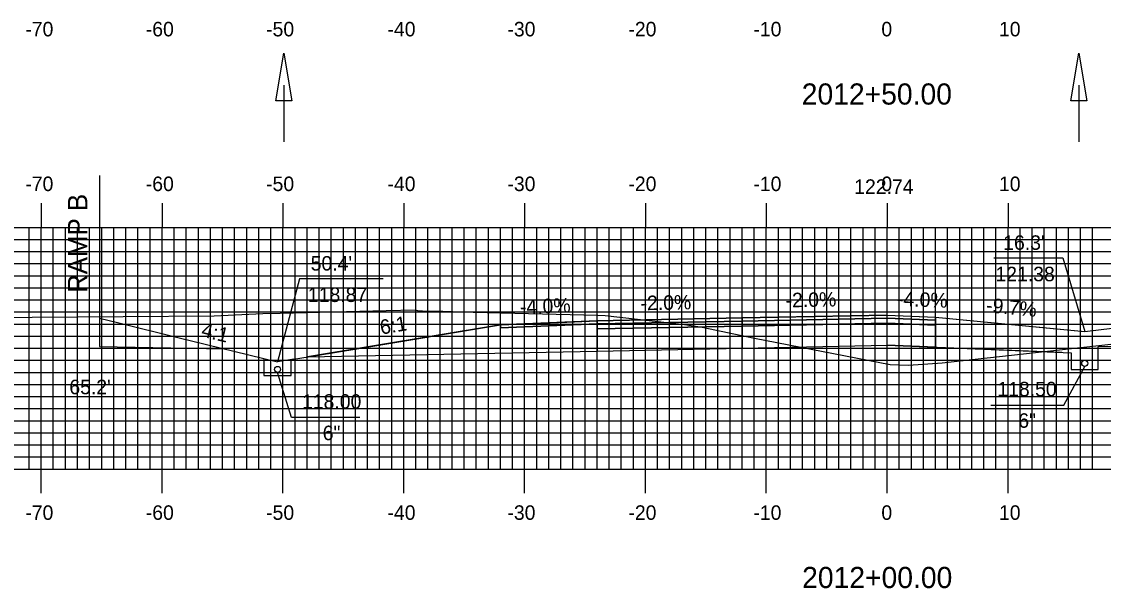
# Model space of a CAD drawing. Extents: x 853894 to 854237, y 366605 to 366825.
# Drawn here: x 853987.9 to 854077.4, y 366658.2 to 366705.1 of the extents above; entities that cross this region are included whole.
import ezdxf

# ---------------------------------------------------------------- set-up
doc = ezdxf.new("R2010")
doc.units = 0
for name, color, linetype in [('ANNOTATION', 7, 'Continuous'), ('D_Drainage_Ditch_Line', 7, 'Continuous'), ('D_Drainage_Underdrain', 7, 'Continuous'), ('D_Roadway_Centerline', 7, 'Continuous'), ('D_Roadway_Centerline_Text', 7, 'Continuous'), ('D_Roadway_Edge_Shoulder', 7, 'Continuous'), ('D_Roadway_Edge_TW', 7, 'Continuous'), ('D_Roadway_Pavement', 7, 'Continuous'), ('D_Roadway_SubGrade', 7, 'Continuous'), ('D_Text_Standard', 7, 'Continuous'), ('H_V ANNOTATION', 7, 'Continuous'), ('M_Roadway_Centerline', 7, 'Continuous'), ('MAJOR', 7, 'Continuous'), ('MINOR', 7, 'Continuous'), ('PDRAIN', 7, 'Continuous'), ('S_Roadway_Centerline', 7, 'Continuous')]:
    doc.layers.add(name, color=color, linetype=linetype)

msp = doc.modelspace()

# ---------------------------------------------------------------- linework, layer by layer
at = {"layer": 'ANNOTATION'}
for points in [[(854068.366, 366685.519), (854074.059, 366685.519), (854075.876, 366679.434)], [(854017.83, 366683.805), (854010.901, 366683.805), (854009.083, 366676.921)], [(854015.894, 366672.321), (854010.23, 366672.321), (854009.083, 366676.055)], [(854068.103, 366673.345), (854074.146, 366673.345), (854075.876, 366676.555)]]:
    msp.add_lwpolyline(points, dxfattribs=at)
at = {"layer": 'D_Drainage_Ditch_Line'}
for p, q in [((854009.597, 366699.83), (854009.597, 366695.131)), ((854075.389, 366699.83), (854075.389, 366695.131))]:
    msp.add_line(p, q, dxfattribs=at)
for points in [[(854010.254, 366698.517), (854008.941, 366698.517), (854009.597, 366702.454)], [(854076.045, 366698.517), (854074.733, 366698.517), (854075.389, 366702.454)]]:
    msp.add_lwpolyline(points, close=True, dxfattribs=at)
at = {"layer": 'D_Drainage_Underdrain'}
msp.add_line((854059.53, 366678.295), (854073.978, 366677.717), dxfattribs=at)
at = {"layer": 'D_Roadway_Centerline'}
for p, q in [((854059.53, 366678.295), (854074.751, 366677.686)), ((854086.982, 366678.363), (854077.001, 366678.158))]:
    msp.add_line(p, q, dxfattribs=at)
for points in [[(853994.353, 366680.533), (853995.833, 366680.17), (854000.84, 366678.943), (854009.083, 366676.921)], [(854010.439, 366677.147), (854015.823, 366678.044), (854027.53, 366679.995), (854027.533, 366679.995), (854033.016, 366680.215), (854035.529, 366680.315), (854035.53, 366680.315), (854047.527, 366680.555), (854047.53, 366680.555), (854051.984, 366680.644), (854059.53, 366680.795), (854059.532, 366680.795), (854061.527, 366680.715), (854063.53, 366680.635), (854063.536, 366680.635), (854073.254, 366679.689), (854075.875, 366679.433), (854075.876, 366679.433)], [(854063.53, 366680.635), (854075.876, 366679.433)], [(854075.876, 366679.434), (854081.528, 366680.12), (854086.982, 366680.783)]]:
    msp.add_lwpolyline(points, dxfattribs=at)
at = {"layer": 'D_Roadway_Edge_Shoulder'}
for points in [[(854059.53, 366680.795), (854063.53, 366680.635), (854063.53, 366680.385), (854059.53, 366680.545)], [(854035.53, 366680.315), (854027.53, 366679.995), (854027.53, 366679.745), (854035.53, 366680.065)]]:
    msp.add_lwpolyline(points, close=True, dxfattribs=at)
at = {"layer": 'D_Roadway_Edge_TW'}
for points in [[(854047.53, 366680.555), (854035.53, 366680.315), (854035.53, 366680.065), (854047.53, 366680.305)], [(854059.53, 366680.795), (854047.53, 366680.555), (854047.53, 366680.305), (854059.53, 366680.545)]]:
    msp.add_lwpolyline(points, close=True, dxfattribs=at)
at = {"layer": 'D_Roadway_Pavement'}
for points in [[(854059.53, 366680.545), (854047.53, 366680.305), (854047.53, 366679.889), (854059.53, 366680.129)], [(854059.53, 366680.545), (854063.53, 366680.385), (854063.53, 366679.969), (854059.53, 366680.129)], [(854047.53, 366680.305), (854035.53, 366680.065), (854035.53, 366679.649), (854047.53, 366679.889)], [(854035.53, 366680.065), (854035.53, 366679.649), (854035.53, 366679.649)]]:
    msp.add_lwpolyline(points, close=True, dxfattribs=at)
msp.add_lwpolyline([(854047.53, 366680.305), (854047.53, 366679.889)], dxfattribs=at)
at = {"layer": 'D_Roadway_SubGrade'}
for p, q in [((853994.353, 366692.342), (853994.353, 366678.2)), ((853994.353, 366680.533), (853994.353, 366678.2)), ((854010.439, 366677.147), (854009.083, 366676.921))]:
    msp.add_line(p, q, dxfattribs=at)
for points in [[(854059.53, 366680.129), (854063.53, 366679.969), (854063.53, 366680.385), (854063.53, 366680.635), (854063.53, 366678.135), (854059.53, 366678.295)], [(854035.53, 366679.649), (854035.53, 366679.649), (854035.53, 366680.065), (854027.53, 366679.745), (854027.53, 366679.995), (854011.576, 366677.336), (854035.53, 366677.815)], [(854047.53, 366679.889), (854035.53, 366679.649), (854035.53, 366677.815), (854047.53, 366678.055)], [(854059.53, 366680.129), (854047.53, 366679.889), (854047.53, 366678.055), (854059.53, 366678.295)]]:
    msp.add_lwpolyline(points, close=True, dxfattribs=at)
msp.add_lwpolyline([(853994.353, 366678.2), (854004.653, 366678.008)], dxfattribs=at)
at = {"layer": 'MAJOR'}
for p, q in [((853989.53, 366690.059), (853989.53, 366688.055)), ((853999.53, 366690.059), (853999.53, 366688.055)), ((854009.53, 366690.059), (854009.53, 366688.055)), ((854019.53, 366690.059), (854019.53, 366688.055)), ((854029.53, 366690.059), (854029.53, 366688.055)), ((854039.53, 366690.059), (854039.53, 366688.055)), ((854049.53, 366690.059), (854049.53, 366688.055)), ((854059.53, 366690.059), (854059.53, 366688.055)), ((854069.53, 366690.059), (854069.53, 366688.055)), ((853919.53, 366688.055), (854199.53, 366688.055)), ((853919.53, 366688.055), (854199.53, 366688.055)), ((853989.53, 366668.055), (853989.53, 366688.055)), ((853999.53, 366668.055), (853999.53, 366688.055)), ((854009.53, 366668.055), (854009.53, 366688.055)), ((854019.53, 366668.055), (854019.53, 366688.055)), ((854029.53, 366668.055), (854029.53, 366688.055)), ((854039.53, 366668.055), (854039.53, 366688.055)), ((854049.53, 366668.055), (854049.53, 366688.055)), ((854059.53, 366668.055), (854059.53, 366688.055)), ((854069.53, 366668.055), (854069.53, 366688.055)), ((853919.53, 366683.055), (854199.53, 366683.055)), ((853919.53, 366678.055), (854199.53, 366678.055)), ((853919.53, 366673.055), (854199.53, 366673.055)), ((853919.53, 366668.055), (854199.53, 366668.055)), ((853919.53, 366668.055), (854199.53, 366668.055)), ((853989.53, 366666.051), (853989.53, 366668.055)), ((853999.53, 366666.051), (853999.53, 366668.055)), ((854009.53, 366666.051), (854009.53, 366668.055)), ((854019.53, 366666.051), (854019.53, 366668.055)), ((854029.53, 366666.051), (854029.53, 366668.055)), ((854039.53, 366666.051), (854039.53, 366668.055)), ((854049.53, 366666.051), (854049.53, 366668.055)), ((854059.53, 366666.051), (854059.53, 366668.055)), ((854069.53, 366666.051), (854069.53, 366668.055))]:
    msp.add_line(p, q, dxfattribs=at)
at = {"layer": 'MINOR'}
for p, q in [((853988.53, 366668.055), (853988.53, 366688.055)), ((853990.53, 366668.055), (853990.53, 366688.055)), ((853991.53, 366668.055), (853991.53, 366688.055)), ((853992.53, 366668.055), (853992.53, 366688.055)), ((853993.53, 366668.055), (853993.53, 366688.055)), ((853994.53, 366668.055), (853994.53, 366688.055)), ((853995.53, 366668.055), (853995.53, 366688.055)), ((853996.53, 366668.055), (853996.53, 366688.055)), ((853997.53, 366668.055), (853997.53, 366688.055)), ((853998.53, 366668.055), (853998.53, 366688.055)), ((854000.53, 366668.055), (854000.53, 366688.055)), ((854001.53, 366668.055), (854001.53, 366688.055)), ((854002.53, 366668.055), (854002.53, 366688.055)), ((854003.53, 366668.055), (854003.53, 366688.055)), ((854004.53, 366668.055), (854004.53, 366688.055)), ((854005.53, 366668.055), (854005.53, 366688.055)), ((854006.53, 366668.055), (854006.53, 366688.055)), ((854007.53, 366668.055), (854007.53, 366688.055)), ((854008.53, 366668.055), (854008.53, 366688.055)), ((854010.53, 366668.055), (854010.53, 366688.055)), ((854011.53, 366668.055), (854011.53, 366688.055)), ((854012.53, 366668.055), (854012.53, 366688.055)), ((854013.53, 366668.055), (854013.53, 366688.055)), ((854014.53, 366668.055), (854014.53, 366688.055)), ((854015.53, 366668.055), (854015.53, 366688.055)), ((854016.53, 366668.055), (854016.53, 366688.055)), ((854017.53, 366668.055), (854017.53, 366688.055)), ((854018.53, 366668.055), (854018.53, 366688.055)), ((854020.53, 366668.055), (854020.53, 366688.055)), ((854021.53, 366668.055), (854021.53, 366688.055)), ((854022.53, 366668.055), (854022.53, 366688.055)), ((854023.53, 366668.055), (854023.53, 366688.055)), ((854024.53, 366668.055), (854024.53, 366688.055)), ((854025.53, 366668.055), (854025.53, 366688.055)), ((854026.53, 366668.055), (854026.53, 366688.055)), ((854027.53, 366668.055), (854027.53, 366688.055)), ((854028.53, 366668.055), (854028.53, 366688.055)), ((854030.53, 366668.055), (854030.53, 366688.055)), ((854031.53, 366668.055), (854031.53, 366688.055)), ((854032.53, 366668.055), (854032.53, 366688.055)), ((854033.53, 366668.055), (854033.53, 366688.055)), ((854034.53, 366668.055), (854034.53, 366688.055)), ((854035.53, 366668.055), (854035.53, 366688.055)), ((854036.53, 366668.055), (854036.53, 366688.055)), ((854037.53, 366668.055), (854037.53, 366688.055)), ((854038.53, 366668.055), (854038.53, 366688.055)), ((854040.53, 366668.055), (854040.53, 366688.055)), ((854041.53, 366668.055), (854041.53, 366688.055)), ((854042.53, 366668.055), (854042.53, 366688.055)), ((854043.53, 366668.055), (854043.53, 366688.055)), ((854044.53, 366668.055), (854044.53, 366688.055)), ((854045.53, 366668.055), (854045.53, 366688.055)), ((854046.53, 366668.055), (854046.53, 366688.055)), ((854047.53, 366668.055), (854047.53, 366688.055)), ((854048.53, 366668.055), (854048.53, 366688.055)), ((854050.53, 366668.055), (854050.53, 366688.055)), ((854051.53, 366668.055), (854051.53, 366688.055)), ((854052.53, 366668.055), (854052.53, 366688.055)), ((854053.53, 366668.055), (854053.53, 366688.055)), ((854054.53, 366668.055), (854054.53, 366688.055)), ((854055.53, 366668.055), (854055.53, 366688.055)), ((854056.53, 366668.055), (854056.53, 366688.055)), ((854057.53, 366668.055), (854057.53, 366688.055)), ((854058.53, 366668.055), (854058.53, 366688.055)), ((854060.53, 366668.055), (854060.53, 366688.055)), ((854061.53, 366668.055), (854061.53, 366688.055)), ((854062.53, 366668.055), (854062.53, 366688.055)), ((854063.53, 366668.055), (854063.53, 366688.055)), ((854064.53, 366668.055), (854064.53, 366688.055)), ((854065.53, 366668.055), (854065.53, 366688.055)), ((854066.53, 366668.055), (854066.53, 366688.055)), ((854067.53, 366668.055), (854067.53, 366688.055)), ((854068.53, 366668.055), (854068.53, 366688.055)), ((854070.53, 366668.055), (854070.53, 366688.055)), ((854071.53, 366668.055), (854071.53, 366688.055)), ((854072.53, 366668.055), (854072.53, 366688.055)), ((854073.53, 366668.055), (854073.53, 366688.055)), ((854074.53, 366668.055), (854074.53, 366688.055)), ((854075.53, 366668.055), (854075.53, 366688.055)), ((854076.53, 366668.055), (854076.53, 366688.055)), ((853919.53, 366687.055), (854199.53, 366687.055)), ((853919.53, 366686.055), (854199.53, 366686.055)), ((853919.53, 366685.055), (854199.53, 366685.055)), ((853919.53, 366684.055), (854199.53, 366684.055)), ((853919.53, 366682.055), (854199.53, 366682.055)), ((853919.53, 366681.055), (854199.53, 366681.055)), ((853919.53, 366680.055), (854199.53, 366680.055)), ((853919.53, 366679.055), (854199.53, 366679.055)), ((853919.53, 366677.055), (854199.53, 366677.055)), ((853919.53, 366676.055), (854199.53, 366676.055)), ((853919.53, 366675.055), (854199.53, 366675.055)), ((853919.53, 366674.055), (854199.53, 366674.055)), ((853919.53, 366672.055), (854199.53, 366672.055)), ((853919.53, 366671.055), (854199.53, 366671.055)), ((853919.53, 366670.055), (854199.53, 366670.055)), ((853919.53, 366669.055), (854199.53, 366669.055))]:
    msp.add_line(p, q, dxfattribs=at)
at = {"layer": 'PDRAIN'}
for points in [[(854074.751, 366677.686), (854074.751, 366676.305), (854077.001, 366676.305), (854077.001, 366678.158)], [(854007.958, 366677.197), (854007.958, 366675.805), (854010.208, 366675.805), (854010.208, 366677.143)]]:
    msp.add_lwpolyline(points, dxfattribs=at)
for centre in [(854075.876, 366676.805), (854009.083, 366676.305)]:
    msp.add_circle(centre, 0.25, dxfattribs=at)
at = {"layer": 'S_Roadway_Centerline'}
msp.add_lwpolyline([(853984.895, 366680.569), (853988.77, 366680.635), (854003.848, 366680.732), (854007.868, 366680.925), (854009.288, 366680.954), (854018.07, 366681.17), (854020.462, 366681.235), (854020.671, 366681.167), (854021.089, 366681.157), (854022.749, 366681.131), (854025.264, 366681.038), (854035.592, 366680.777), (854036.203, 366680.759), (854042.765, 366680.013), (854044.217, 366679.796), (854048.545, 366678.887), (854059.769, 366676.712), (854061.295, 366676.64), (854064.084, 366676.852), (854079.27, 366678.526)], dxfattribs=at)

# ---------------------------------------------------------------- texts
at = {"layer": 'ANNOTATION'}
for s, height, rotation, p in [('RAMP B', 1.6, 90, (853993.339, 366682.627)), ('-4.0%', 1.2, 2.29058, (854029.163, 366680.862)), ('-2.0%', 1.2, 1.14577, (854039.134, 366681.188)), ('-2.0%', 1.2, 1.14573, (854051.136, 366681.428)), ('-4.0%', 1.2, 357.70949, (854060.32, 366681.565)), ('-9.7%', 1.2, 354.43916, (854067.673, 366681.041)), ('6:1', 1.2, 9.46087, (854017.66, 366679.178)), ('4:1', 1.2, 346.18377, (854002.705, 366679.039)), ('118.50', 1.2, 360, (854068.646, 366674.071)), ('118.00', 1.2, 360, (854011.11, 366673.047)), ('6"', 1.2, 360, (854070.38, 366671.471)), ('6"', 1.2, 360, (854012.822, 366670.447))]:
    msp.add_text(s, height=height, rotation=rotation, dxfattribs=at).set_placement(p)
for s, p in [("16.3' ", (854069.132, 366686.193)), ("50.4' ", (854011.825, 366684.479)), ('121.38', (854068.489, 366683.593)), ('118.87', (854011.596, 366681.879))]:
    msp.add_text(s, height=1.2, dxfattribs=at).set_placement(p)
at = {"layer": 'D_Roadway_Centerline_Text'}
msp.add_text('122.74', height=1.2, dxfattribs=at).set_placement((854056.801, 366690.825))
at = {"layer": 'D_Text_Standard'}
msp.add_text("65.2'", height=1.2, dxfattribs=at).set_placement((853991.854, 366674.248))
at = {"layer": 'H_V ANNOTATION'}
for s, height, p in [('-70', 1.2, (853988.213, 366703.855)), ('-60', 1.2, (853998.181, 366703.855)), ('-50', 1.2, (854008.138, 366703.855)), ('-40', 1.2, (854018.181, 366703.855)), ('-30', 1.2, (854028.106, 366703.855)), ('-20', 1.2, (854038.117, 366703.855)), ('-10', 1.2, (854048.46, 366703.855)), ('0', 1.2, (854059.048, 366703.855)), ('10', 1.2, (854068.781, 366703.855)), ('2012+50.00', 1.75, (854052.46, 366698.211)), ('-70', 1.2, (853988.213, 366691.055)), ('-60', 1.2, (853998.181, 366691.055)), ('-50', 1.2, (854008.138, 366691.055)), ('-40', 1.2, (854018.181, 366691.055)), ('-30', 1.2, (854028.106, 366691.055)), ('-20', 1.2, (854038.117, 366691.055)), ('-10', 1.2, (854048.46, 366691.055)), ('0', 1.2, (854059.048, 366691.055)), ('10', 1.2, (854068.781, 366691.055)), ('-70', 1.2, (853988.213, 366663.855)), ('-60', 1.2, (853998.181, 366663.855)), ('-50', 1.2, (854008.138, 366663.855)), ('-40', 1.2, (854018.181, 366663.855)), ('-30', 1.2, (854028.106, 366663.855)), ('-20', 1.2, (854038.117, 366663.855)), ('-10', 1.2, (854048.46, 366663.855)), ('0', 1.2, (854059.048, 366663.855)), ('10', 1.2, (854068.781, 366663.855)), ('2012+00.00', 1.75, (854052.492, 366658.211))]:
    msp.add_text(s, height=height, dxfattribs=at).set_placement(p)
at = {"layer": 'M_Roadway_Centerline'}
for s, p in [('C', (854020.457, 366681.235)), ('L', (854020.462, 366681.227))]:
    msp.add_text(s, height=0.0146, dxfattribs=at).set_placement(p)

doc.saveas('drawing.dxf')
